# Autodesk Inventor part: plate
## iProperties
Shininess: 64.0
Length Units: 11272
Angle Units: 11279
Time Units: 11290
Mass Units: 11286
Length Display Precision: 3
Angle Display Precision: 2
Compacted: True
Part Number: plate
Document SubType Name: Modeling
Created: 2002-11
Designer: Elise Moss
Density: 0.0
Volumn: 0.0
Area: 0.0
PropertySet Name: Model Information
Control State: 0
Master: False
Checked Out: False
Author: Elise Moss
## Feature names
1. Extrusion1
